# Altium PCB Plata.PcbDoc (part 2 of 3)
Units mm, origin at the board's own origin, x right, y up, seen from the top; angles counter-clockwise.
Board outline 225.2 x 126.25 mm, 5 copper layers (Top Layer, Mid-Layer 1, Mid-Layer 2, Mid-Layer 3, Bottom Layer); 204 components, 178 nets, 840 pads, 262 vias.
Unrouted connection lines stored in the file: 7.
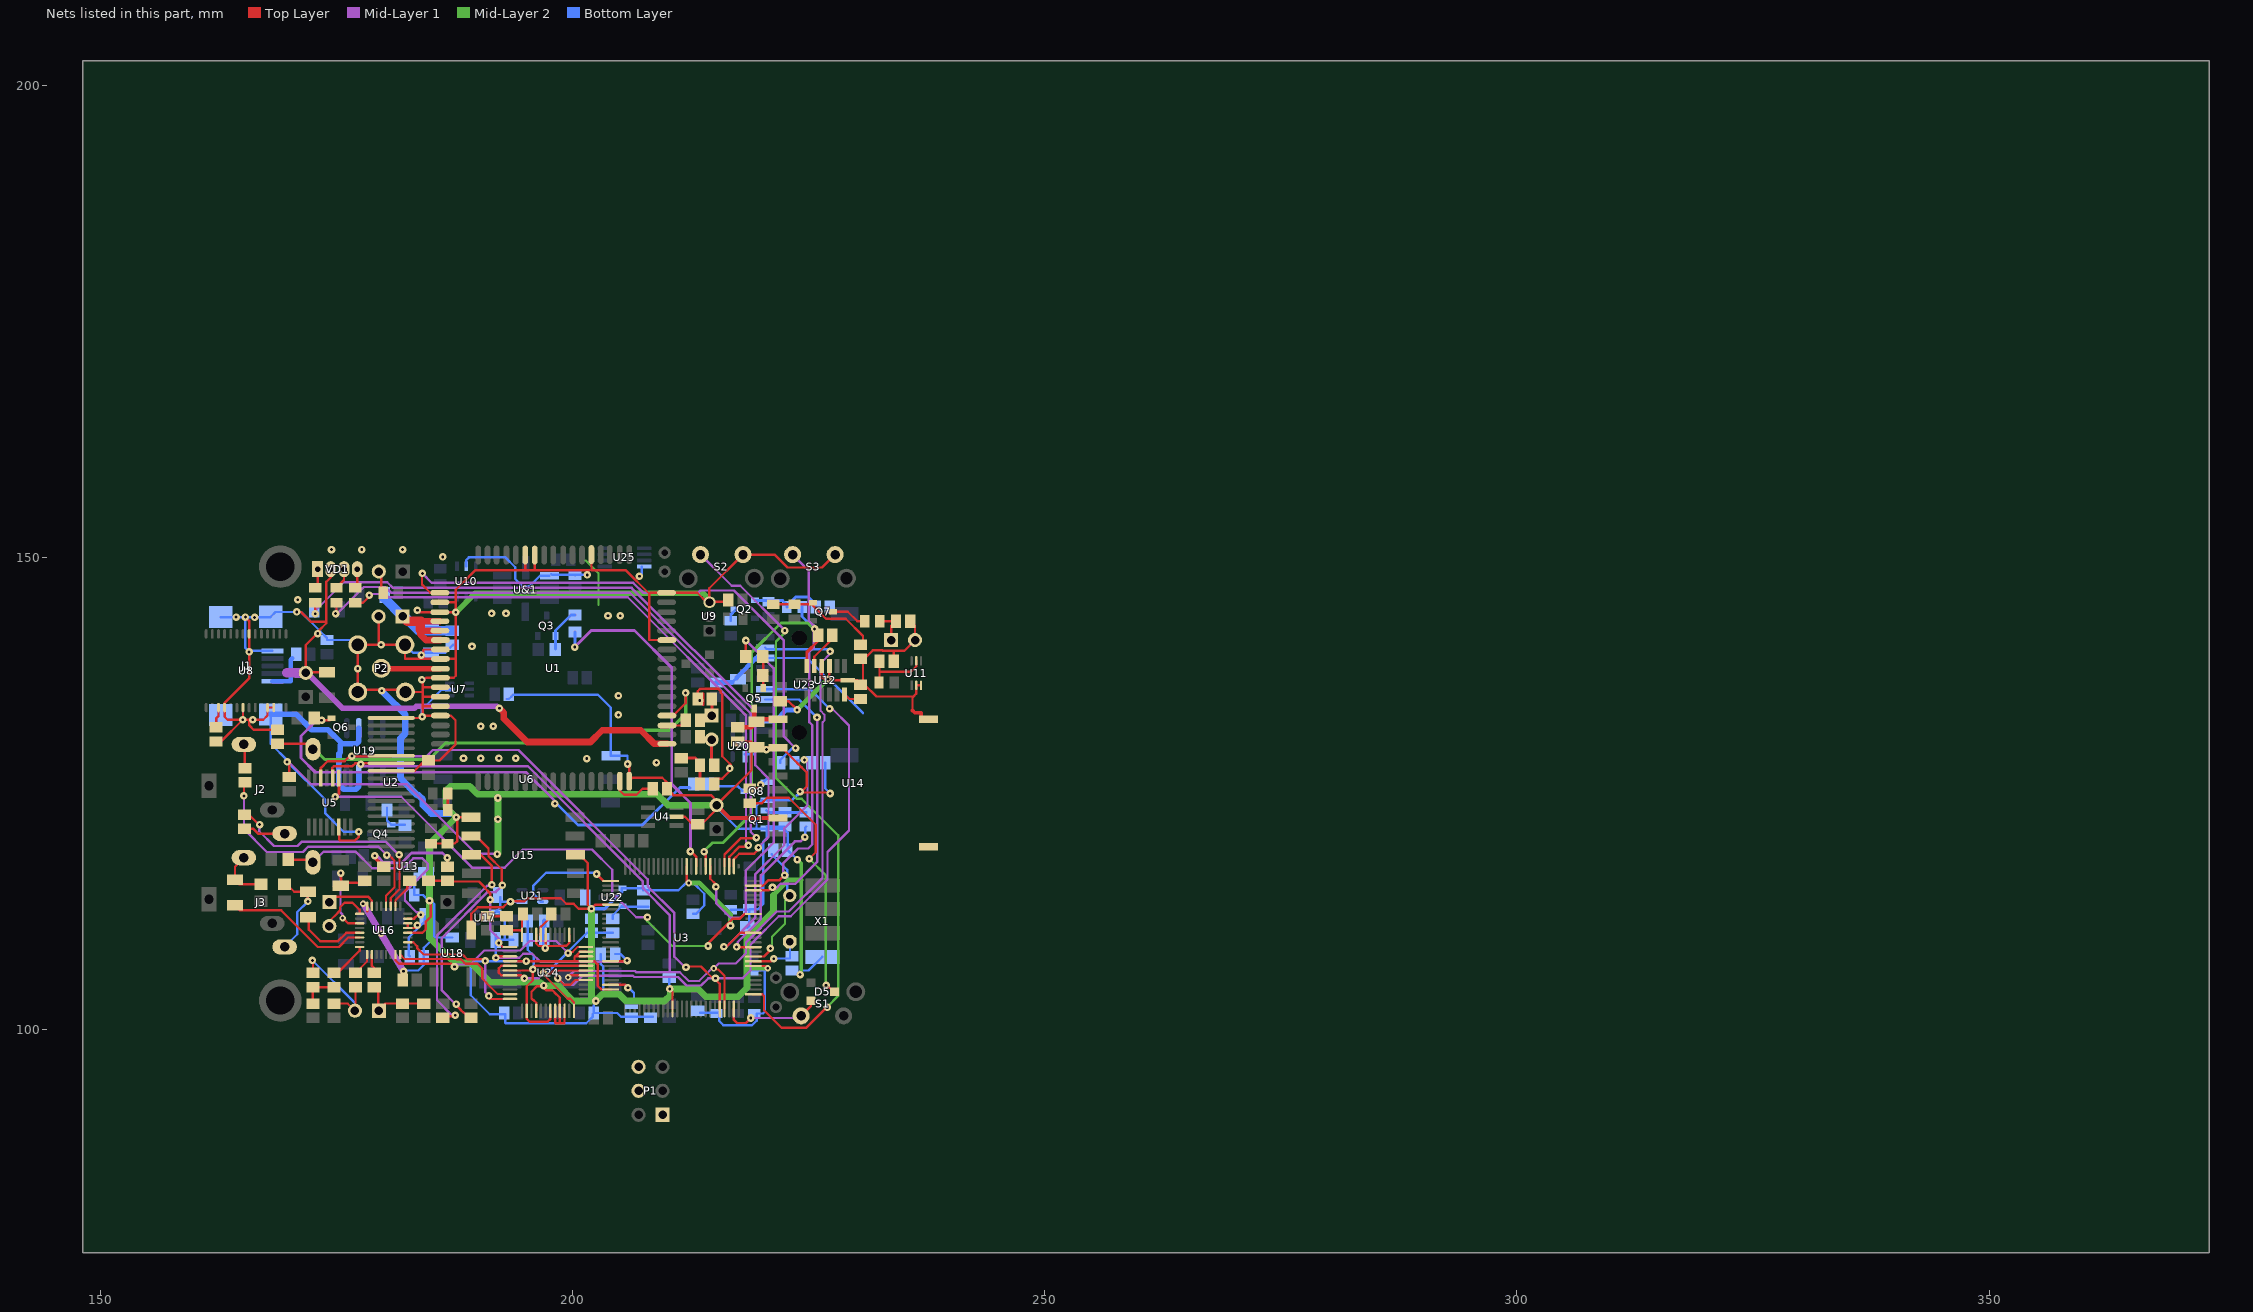
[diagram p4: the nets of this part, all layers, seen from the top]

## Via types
v1: diameter 0.8, hole 0.3, Top Layer to Bottom Layer, 158 vias
v2: diameter 0.8, hole 0.3, Top Layer to Mid-Layer 1, 69 vias
v3: diameter 0.8, hole 0.3, Mid-Layer 2 to Bottom Layer, 18 vias
v4: diameter 0.7, hole 0.3, Top Layer to Bottom Layer, 9 vias
v5: diameter 0.7, hole 0.3, Top Layer to Mid-Layer 1, 5 vias
v6: diameter 0.8, hole 0.3, Top Layer to Mid-Layer 1, tented top, 1 vias
v7: diameter 0.8, hole 0.3, Top Layer to Bottom Layer, tented top, 1 vias
v8: diameter 1, hole 0.5, Top Layer to Bottom Layer, 1 vias

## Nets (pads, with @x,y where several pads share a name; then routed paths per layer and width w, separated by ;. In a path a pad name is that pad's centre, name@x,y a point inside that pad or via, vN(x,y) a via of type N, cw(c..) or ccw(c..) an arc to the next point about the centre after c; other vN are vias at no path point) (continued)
GND: BT1.2 C1.1 C2.2 C3.2 C4.2 C5.2 C6.1 C7.1 C11.1 C12.2 C13.1 C14.2 C15.1 C16.2 C17.2 C18.1 C19.1 C20.2 C21.1 C22.1 C23.1 C24.1 C25.2 C26.1 C28.1 C31.2 C34.2 C38.2 C39.2 C43.1 C47.1 C48.2 C51.1 C55.1 C56.2 C57.2 C59.2 C60.1 C61.2 C62.2 C63.2 C64.2 C65.1 C66.1 C67.2 C68.1 C72.2 C73.2 D2.2 D4.1 J1.5 J1.MH1 J1.MH2 J1.MH3 J1.MH4 LS1.2 P1.6 P2.2 P2.3 P2.4 P2.5 Q1.2 Q8.2 R7.2 R8.2 R13.1 R14.1 R15.1 R16.1 R25.2 R49.1 R51.2 R56.1 S2.1 S3.1 U1.17 U1.29 U1.34 U1.39 U1.45 U1.46 U1.53 U1.54 U1.58 U1.59 U1.61 U1.62 U1.63 U1.64 U1.65 U2.1 U2.8 U3.11 U3.32 U3.62 U3.81 U3.99 U4.2 U5.6 U6.6 U7.2 U8.7 U8.18 U8.21 U8.25 U8.26 U9.3 U10.2 U11.2 U11.3 U12.7 U12.10 U12.11 U13.1 U14.3 U14.8 U14.11 U14.12 U15.3 U15.6 U16.12 U16.24 U17.1 U18.2 U19.3 U19.6 U20.1 U21.1 U22.1 U23.6 U23.9 U24.4 U24.16 U24.20 U24.21 U24.22 U24.33 U24.34 U24.35 U25.4 U&1.1 VD1.3 X1.8 | length 850.4
  Top Layer w0.25: C19.1@162.775,130.5 v1(165.075,132.8) ; U8.21@165.1,134.1 165.1,132.825 v1(165.075,132.8) ; v1(165.35,143.675) 165.75,143.275 U8.7@165.75,141.9 v1(165.75,140) 165.75,137.175 163.15,134.575 U8.18@163.15,134.1 163.15,133.125 163.475,132.8 v1(165.075,132.8) ; U8.26@168.35,134.1 U8.25@167.7,134.1 167.7,133.25 167.25,132.8 v1(166.125,132.8) v1@165.775,132.8 ; C43.1@168.75,131.75 166.225,131.75 165.775,132.2 v1@165.775,132.8 ; C14.2@170,126.75 v1@170,128.3 ; v1(170.8,144.225) 171.25,144.225 172.293,143.182 173.925,143.182 ; BT1.2@171.75,137.77 171.75,140.725 172.826,141.801 173.025,141.801 173.149,141.801 173.149,141.925 173.149,142.249 173.925,143.025 173.925,143.182 ; BT1.2@171.83,137.85 C62.2@174,137.85 ; VD1.3@174.4,148.75 174.4,147.88 173.925,147.405 173.925,143.182 ; U5.6@175.202,121.4 175.215,121.387 175.275,121.327 175.275,120.125 175.375,120.025 176.975,120.025 177.35,120.4 v1(177.35,120.95) ; v5@177.75,113.55 177.9,113.4 U16.24@178.25,113.05 178.25,112.532 ; v1@179.46,140.815 C2.2@179.46,143.75 ; U2.8@180.8,127.4 183.275,127.4 184.375,128.5 C5.2@184.75,128.5 185.905,128.5 187.6,130.195 187.6,132.75 187.1,133.25 U1.65@186,133.25 v1@184.17,133.25 ; U2.1@180.8,133 183.88,133 184.04,133.16 184.15,133.27 184.15,136.925 184.162,136.938 184.475,137.25 U1.61@186,137.25 187.4,137.25 187.625,137.475 v1(187.625,144.2) 187.625,146.575 189.675,148.625 201.55,148.625 201.8,148.625 ; C57.2@182,105.25 182,106.175 v1@182,106.25 ; U16.12@182.55,110.25 184.1,110.25 184.47,110.62 184.47,111.445 184.94,111.915 ; v1@183.688,144.287 183.775,144.2 U1.54@185.95,144.2 v1@187.575,144.2 ; 184.1,135.75 P2.3@182.3,135.75 182.05,136 179.8,136 177.25,136 v1(177.25,138.225) P2.5@177.25,140.75 v1(179.725,140.75) P2.4@182.25,140.75 182.25,139.25 184,139.25 184.2,139.25 ; 184.175,135.25 U1.63@186,135.25 ; 184.2,134.25 U1.64@186,134.25 ; 184.2,136.25 U1.62@186,136.25 ; 184.984,111.931 v1@184.984,113.291 ; R16.1@185,119.7 R15.1@186.75,119.7 187.525,119.7 187.8,119.975 v1@187.8,122.391 ; U1.53@185.95,145.25 187.55,145.25 ; U1.58@186,140.25 184.275,140.25 184.2,140.175 184.2,139.65 184.2,139.25 ; R14.1@186.8,123.25 R13.1@186.8,125 ; 187.625,139.25 U1.59@186,139.25 184.2,139.25 ; v1@187.909,122.5 U15.6@189.25,122.5 ; U18.2@189.282,110.54 189.282,112.257 189.975,112.95 192.65,112.95 v1@193.288,113.587 ; U24.4@193.375,107.25 v1(195.1,107.25) 200.2,107.25 ; v1@193.425,113.587 194.913,113.587 195.225,113.9 198.75,113.9 199.325,113.325 200.115,113.325 200.64,112.8 v1(202,112.8) ; 195,148.725 U1.46@195,150.25 ; 195.825,103.125 195.65,103.3 195.65,104.004 196.246,104.6 v1@196.775,104.6 ; 195.857,103.125 196.15,102.832 ; 196,148.725 U1.45@196,150.25 ; U24.16@196.15,101.975 196.15,102.8 ; v1@196.838,104.537 197.2,104.175 197.85,104.175 198.314,103.711 ; U24.20@198.15,101.975 198.15,100.75 198.25,100.65 199.125,100.65 199.15,100.675 U24.22@199.15,101.975 ; 198.325,103.711 198.65,103.386 U24.21@198.65,101.975 198.65,100.65 ; U15.3@200.3,118.5 200.725,118.5 201.6,117.625 201.6,113.2 v1(202,112.8) ; U24.34@201.425,107.75 200.3,107.75 ; U24.35@201.425,108.25 200.8,108.25 200.3,107.75 ; U1.39@202,150.3 202,148.625 205.65,148.625 208.125,146.15 ; U3.99@204.036,104.236 203.054,104.236 202.65,104.64 202.65,106.9 202.3,107.25 U24.33@201.425,107.25 200.2,107.25 ; U3.81@204.036,113.236 202.436,113.236 v1(202,112.8) ; v1(205.825,128.125) 206,127.95 U1.17@206,126.3 ; 206,127.4 U1.17@206,126.3 ; U1.29@210,141.25 208.125,141.25 208.125,146.15 ; U3.11@210.586,102.186 210.586,104.014 ; U4.2@211,122.55 211.875,122.55 212.675,121.75 C6.1@213.029,121.75 ; v4@212.086,115.525 U3.62@212.086,117.286 ; C6.1@213.25,121.75 213.675,121.75 215.25,123.325 LS1.2@215.25,123.77 ; U9.3@214.225,145.225 213.2,146.25 U1.34@209.95,146.25 208.225,146.25 208.125,146.15 ; U9.3@214.45,145.475 U9.3@214.475,145.475 ; C20.2@216.375,145.3 214.5,145.3 214.45,145.3 U9.3@214.475,145.475 ; C39.2@217.5,130.5 218.9,130.5 C38.2@219.5,129.9 219.55,129.85 220.525,129.85 U14.3@221.75,129.85 ; C38.2@218.95,129.6 218.95,127.47 LS1.2@215.25,123.77 ; U3.32@219.136,106.736 v4@220.675,106.736 ; U14.3@221.85,129.75 U14.3@221.75,129.85 ; C31.2@222,134.75 222.9,134.75 v1@223.7,133.95 ; U14.3@222.525,129.5 U14.3@222.525,129.505 ; U14.3@222.525,129.75 U14.3@222.525,129.505 ; U14.3@222.6,130.025 221.925,130.025 U14.3@221.75,129.85 ; v1@223.975,125.1 224.1,125.1 v1@224.15,125.1 ; v1@224.087,125.037 v1@224.15,125.1 ; U12.11@226.4,138.5 226.4,137.35 226.75,137 227.075,137 U12.7@229.15,137 230.175,137 230.588,136.587 230.675,136.5 230.95,136.5 232.175,135.275 236.1,135.275 ; v1@226.9,125.1 v1@224.15,125.1 ; v1@227.2,137.025 227.2,137.1 U12.10@227.2,138.5 ; S3.1@227.8,150.3 226.425,148.925 222.77,148.925 221.395,150.3 S2.1@218.05,150.3 214.475,146.725 U9.3@214.475,145.475 ; C28.1@231,136.5 230.75,136.75 230.75,139.25 230.875,139.25 231.78,140.155 232.795,140.155 232.825,140.125 235.145,140.125 D2.2@236.27,141.25 236.27,142.73 C55.1@235.75,143.25 ; C25.2@234,139 234,140.105 ; 236,133.775 236,135.175 236.1,135.275 ; U11.3@236.9,136.45 U11.2@236.4,136.45 236.4,135.575 236.1,135.275 ; U14.12@236.925,132.85 U14.12@237.7,132.85 ; v1(165.075,132.8) v1@165.775,132.8 ; 200.2,107.25 200.2,107.65 200.3,107.75 ; U1.17@206,126.3 206.375,126.675 209.5,126.675 210,126.175 C7.1@210,125.5 210.675,124.825 214.65,124.825 215.25,124.225 LS1.2@215.25,123.77 ; U14.3@221.75,129.85 222.18,129.85 U14.3@222.525,129.505 ; U14.3@222.525,129.505 223.775,128.255 223.775,128.229 224.229,127.775 224.255,127.775 224.8,127.23 224.8,125.75 224.175,125.125 v1@224.15,125.1
  Top Layer w0.4: LS1.2@215.25,123.77 216.62,122.4 219.836,122.4 ; 219.55,122.4 219.836,122.4 ; U14.8@221.75,122.4 219.836,122.4 ; 236,133.775 236.231,133.544 236.925,133.544 U14.12@236.925,132.85
  Mid-Layer 1 w0.25: v1@170,128.3 172.325,125.975 182.425,125.975 189.775,118.625 v1@191.7,118.625
  Mid-Layer 1 w0.6: BT1.2@171.557,138.093 171.815,137.835 171.9,137.75 174.282,135.368
  Mid-Layer 1 w0.7: v5(177.825,113.325) v4(179.719,110.157) 179.77,110.073 v1(182.1,106.175)
  Mid-Layer 1 w1: 169.75,137.77 BT1.2@171.75,137.77 ; 170.675,137.75 171.75,137.75 BT1.2@171.9,137.75
  Mid-Layer 2 w0.25: 201.4,149.675 202.75,148.325 202.75,146.2 202.75,145 ; v1@227.025,137.1 v1(227.075,137.1)
  Mid-Layer 2 w0.4: v1(223.8,118) 224.225,117.575 v1@224.225,105.95
  Mid-Layer 2 w0.5: v4(212.3,115.525) 213.425,115.525 216.725,112.225 v3(216.725,111) ; 218.525,106.5 v4(220.675,106.5) ; 221.275,114.225 222.9,115.85 224.225,115.85 ; v1(223.775,133.85) v1@227.025,137.1
  Mid-Layer 2 w0.6: v1@187.65,144.175 189.675,146.2 213.8,146.2 U9.3@214.5,145.5
  Mid-Layer 2 w0.7: v1@192.1,118.65 192.1,124.925 ; 196.461,105 191.3,105 189.25,107.05 187.525,107.05 184.85,109.725 v1(184.85,113.65) 184.85,119.65 v1(187.675,122.475) 186.6,123.55 186.6,125.3 187.05,125.75 189.125,125.75 189.95,124.925 192.1,124.925 ; 196.511,104.95 196.65,104.95 v1(196.95,104.65) 198.45,104.65 200.075,103.025 v3(202.475,103.025) 202,103.5 v1(202,112.8) ; v3@202.475,103.072 203.161,103.758 204.917,103.758 205.65,103.025 209.75,103.025 210.357,103.632 v1@210.357,103.943 ; v1(210.3,104.3) 213.311,104.3 214.136,103.475 217.519,103.475 218.475,104.431 218.475,109.725 221.275,112.525 221.275,114.225 ; LS1.2@215.25,123.77 210.109,123.77 208.954,124.925 192.1,124.925
  Bottom Layer w0.25: J1.MH3@162.737,143.675 v1(164.375,143.675) v1(165.35,143.675) ; J1.MH1@167.988,133.325 J1.MH1@168.038,133.375 168.038,130.262 v1@169.862,128.438 ; J1.5@168.213,140.1 165.75,140.1 165.65,140.1 165.35,140.4 v1(165.35,143.675) ; v1(169.775,128.35) 169.821,128.35 173.825,124.346 173.825,122.875 175.75,120.95 v1(177.35,120.95) ; P2.5@177.25,140.75 176.75,141.25 C18.1@174,141.25 174,141.475 173.287,142.188 171.25,144.225 v1(170.8,144.225) 168.538,144.225 J1.MH4@168.038,143.725 167.988,143.675 166.325,143.675 v1(165.35,143.675) ; v1@182,106.25 182.1,106.25 183.65,106.25 184.25,106.85 C34.2@184.25,107.75 184.25,108.65 185.35,109.75 ; P2.4@182.25,140.75 183.1,139.9 184,139.9 C4.2@185,139.9 186.5,139.9 187.3,140.7 C3.2@187.35,140.75 ; U13.1@183.45,116.2 183.25,116 C26.1@183.25,114.25 184.15,114.25 v1@184.65,113.75 ; v1@183.975,133.075 184.025,133.125 184.025,133.875 186.15,136 U7.2@186.98,136 ; v1@185,113.65 185.35,113.3 185.35,109.75 ; C48.2@187.25,109.75 185.35,109.75 ; 188.025,107.25 191.85,107.25 ; U10.2@188.75,149.05 188.75,149.725 189.025,150 192.888,150 193.925,148.963 193.925,147.725 194.7,146.95 195.45,146.95 196.55,148.05 U&1.1@197.55,148.05 ; 189.209,107.191 189.209,103.641 191.225,101.625 192.75,101.625 192.875,101.625 192.875,100.725 192.925,100.675 200.045,100.675 201.455,100.675 202.125,101.345 C72.2@202.125,101.625 ; C51.1@191.85,109.75 C51.1@191.85,109.5 ; C51.1@191.85,110.059 C51.1@191.85,109.5 ; C47.1@192.35,114 C47.1@192.35,113.55 ; 192.825,109.5 192.825,111.825 192.2,112.45 U17.1@191.85,112.45 192.35,112.95 C47.1@192.35,113.55 ; C13.1@193,135 193.25,135 193.5,135.25 193.725,135.475 202.675,135.475 204.05,134.1 U6.6@204.05,129 205.825,129 v1(205.825,128.125) ; C65.1@193.75,109.5 C51.1@191.85,109.5 ; U21.1@194.65,113.55 v1(193.425,113.55) C47.1@192.35,113.55 ; v1(195.1,107.25) 191.85,107.25 ; U&1.1@197.75,148.25 197.85,148.15 C21.1@200.25,148.15 ; C21.1@200.275,148.125 C21.1@200.25,148.15 ; v1(201.55,148.15) C21.1@200.25,148.15 ; C68.1@202,111.75 v1(202,112.8) ; R56.1@203,108 203,106.925 203.245,106.68 203.245,103.595 202.575,102.925 202.25,102.6 C72.2@202.25,101.75 204.725,101.75 205.125,101.35 206.25,101.35 208.25,101.35 R51.2@208.5,101.35 ; 205.2,114.6 205.2,114.95 U22.1@205.3,114.95 207.5,114.95 207.55,114.95 C63.2@207.625,114.875 ; v1(207.075,148) 207.325,148.25 U25.4@207.325,149.025 ; C63.2@207.5,114.75 211.225,114.75 212,115.525 v4(212.3,115.525) 212.8,115.525 213.95,114.375 213.95,113.142 213.058,112.25 C22.1@212.75,112.25 ; v1@210.25,104.35 C24.1@210.25,105.5 ; C11.1@213.525,101.775 215.25,101.775 215.475,101.775 215.525,101.725 215.525,101.7 215.525,100.9 215.975,100.45 219,100.45 219.5,100.95 219.5,101.7 220.168,101.7 220.35,101.882 220.35,106.15 ; LS1.2@215.25,123.77 215.25,123.55 217.525,121.275 219.475,121.275 ; v3(216.725,111) 216.725,112.675 R49.1@216.75,112.7 218.7,112.7 218.7,110.95 D4.1@218.5,110.75 ; C66.1@216.9,136.75 C66.1@217.375,137.225 ; U20.1@218.25,129.15 219.15,129.15 219.65,129.65 v1(220.525,129.65) ; C61.2@218.75,112.75 219.625,112.75 220.175,113.3 220.175,119.85 220.55,120.225 Q1.2@220.55,121.275 ; C23.1@219,106.25 v4@220.45,106.25 ; U23.6@219.443,139.35 U23.6@220.4,139.35 224.825,139.35 v1(227.075,137.1) ; Q8.2@220.075,124.3 219.475,123.7 219.475,121.275 ; Q1.2@220.55,121.3 Q1.2@220.55,121.275 ; Q1.2@220.55,121.5 R8.2@222.5,121.5 ; Q8.2@220.55,124.3 223.25,124.3 223.75,124.8 223.85,124.8 ; v1(223.8,118) 222.775,119.025 222.775,120.875 222.375,121.275 Q1.2@220.55,121.275 ; 224.1,106.25 225,106.25 X1.8@226.45,107.7 ; R7.2@226.75,128.25 226.75,125.525 v1(227.275,125) ; v1@227.3,136.975 230.763,133.513 ; 191.85,107.25 C51.1@191.85,109.5 ; 219.475,121.275 Q1.2@220.55,121.275
  Bottom Layer w0.4: v1(202,112.8) 203.4,112.8 205.2,114.6
  Bottom Layer w0.5: C67.2@215.25,136.75 C66.1@216.9,136.75 ; C66.1@217.375,137.225 217.375,137.282 U23.6@219.443,139.35 ; U23.9@220.4,132.75 221.55,132.75 222.65,133.85 v1(223.775,133.85)
  Bottom Layer w0.6: J1.MH1@168.038,133.375 170.75,133.375 172.375,131.75 174.108,131.75 175.577,130.28 ; 175.3,129.249 175.275,129.224 ; U19.3@177.365,127.1 177.365,125.74 177.075,125.45 175.743,125.45 175.245,125.948 175.245,128.252 175.275,128.282 175.275,129.224 ; U19.6@177.365,131.9 177.365,130.515 177.1,130.25 175.547,130.25 175.395,130.098 175.395,129.344 175.275,129.224
  Bottom Layer w0.7: v1@180.063,135.587 182.3,133.35 182.3,131.361 181.775,130.836 181.775,126.611 183.586,124.8 ; 183.706,124.8 184.15,124.356 184.15,123.751 185.026,122.875 187.275,122.875
  other v1: 224.1,105.825 192.025,118.575 192.1,122.275 192.1,124.525 224.1,125.2 201.5,128.7 188.45,128.725 190.275,128.725 192.2,128.725 193.975,128.725 190.275,132.125 191.6,132.125 184.075,133.125 204.85,133.325 204.85,135.35 179.8,135.875 184.05,137.05 184,139.65 189.35,140.575 173.025,141.925 166.325,143.65 203.75,143.825 205.05,143.825 191.425,144.075 192.95,144.075 183.575,144.4 170.9,145.525 186.25,150.05 174.475,150.825 177.675,150.825 182,150.825
GND1: C10.1 R23.1 U1.18 | length 58.6
  Top Layer w0.25: 213.825,134.375 213.825,134.85 213.825,135 213.825,135.575 213.288,135.037 R23.1@213.25,135 213.25,135.825 213.5,136.075 213.525,136.075 215.455,136.075 215.675,135.855 215.675,135.682 215.85,135.507 215.85,133.45 ; C10.1@215,126.5 215.075,126.575 215.85,126.575 216.65,127.375 v1(216.65,127.65) 216.65,128.15 ; 215.85,134.155 215.85,133.45 ; v1@216.775,128.025 216.65,128.15 ; 215.85,133.45 215.85,128.95 216.65,128.15
  Top Layer w0.7: v1(192.25,134.025) 192.712,133.563 192.712,132.938 195.2,130.45 201.9,130.45 203.15,131.7 207.225,131.7 208.675,130.25 U1.18@210,130.25
  Mid-Layer 1 w0.6: 172.9,136.75 175.625,134.025 183.25,134.025 183.45,134.225 191.975,134.225 v1@192.212,133.987
  other v1: 208.875,128.275 213.475,134.85
GPIO: J3.5 R40.2 U16.15 | length 25.5
  Top Layer w0.25: R40.2@169.9,118 172.2,118 J3.5@172.5,117.7 ; U16.15@182.55,111.75 183.225,111.75 183.632,112.157 183.918,112.157 183.921,112.154 183.925,112.15 v2(183.918,112.15)
  Mid-Layer 1 w0.25: J3.5@172.5,117.7 173.645,118.845 177.009,118.845 178.779,117.075 182.077,117.075 183.127,118.125 184.1,118.125 184.675,117.55 184.675,117 182.25,114.575 182.25,113.668 183.488,112.431 183.616,112.431 v2@183.896,112.15
GPS_ON: R35.2 U3.57 | length 41
  Top Layer w0.25: U3.57@214.586,117.286 214.586,115.964 215.175,115.375 v2(215.175,115.125) ; R35.2@218.35,139.5 v2(218.35,141.2)
  Mid-Layer 1 w0.25: v2@215.225,114.975 215.225,113.35 216.75,111.825 217.75,111.825 218.335,112.41 218.335,116.849 219.986,118.5 219.996,118.5 221.3,119.804 221.3,138.25 v2(218.35,141.2)
GSM_ON: R6.1 U3.36 | length 17.7
  Top Layer w0.25: v2(217.375,108.75) 217.389,108.736 U3.36@219.136,108.736
  Mid-Layer 1 w0.25: v2@217.5,108.95 217.5,109.267 219.945,111.712 219.945,116.328 223.542,119.925 224.15,119.925 v1(224.6,120.375)
  Bottom Layer w0.25: v1@224.65,120.375 224.65,121.4 R6.1@224.75,121.5
GSM_SPK1: C43.2 J2.5 U1.21 | length 51.5
  Top Layer w0.25: C43.2@168.75,130.25 171.95,130.25 J2.5@172.5,129.7 ; U1.21@210,133.25 210.1,133.35 210.775,133.35 211.975,134.55 v1@211.975,135.45
  Mid-Layer 2 w0.25: J2.5@172.5,129.7 J2.5@172.675,129.7
  Mid-Layer 2 w0.35: J2.5@172.675,129.7 173.775,128.6 184.825,128.6 186.575,130.35 201.8,130.35 203.15,131.7 210.225,131.7 211.975,133.45 v1(211.975,135.65)
HP_OUT_L: C49.1 U16.30 | length 15.4
  Top Layer w0.25: C49.1@164.25,113.15 164.775,112.625 169.15,112.625 173.025,108.75 175.254,108.75 176.254,109.75 U16.30@177.45,109.75
HP_OUT_R: C50.1 U16.29 | length 7.6
  Top Layer w0.25: C50.1@172.075,111.975 172.075,111.9 172.075,110.575 173.285,109.365 175.162,109.365 176.047,110.25 U16.29@177.45,110.25
I2C_AUDIO_CLK: U16.8 U24.11 | length 14
  Top Layer w0.22: U16.8@181.75,107.95 182.24,107.46 187.7,107.46 ; 190.92,104.905 192.075,103.75 U24.11@193.375,103.75
  Top Layer w0.24: 187.7,107.46 188.154,107.46 188.657,106.957 189.935,106.957 190.425,106.467 190.425,105.4 190.92,104.905
I2C_AUDIO_DAC: U16.10 U24.12 | length 15.2
  Top Layer w0.22: v2@191.2,103.25 U24.12@193.375,103.25
  Top Layer w0.24: U16.10@182.55,109.25 182.555,109.245 183.13,109.245 183.539,108.836 183.539,108.636 184.235,107.94 187.487,107.94 187.497,107.95 188.357,107.95 188.86,107.447 190.578,107.447 v2(190.75,107.275)
  Mid-Layer 1 w0.22: v2(190.75,107.275) 190.75,103.95 v2(191.129,103.571)
I2C_AUDIO_LR: U16.7 U24.36 | length 23.2
  Top Layer w0.22: U16.7@181.25,107.95 181.25,107.35 181.62,106.98 ; v2@199.525,108.225 200.025,108.225 200.55,108.75 U24.36@201.425,108.75
  Top Layer w0.24: 181.62,106.98 187.17,106.98 v2(187.5,106.65)
  Mid-Layer 1 w0.22: v2@187.638,106.83 187.723,106.915 187.765,106.915 187.75,106.9 189.175,106.9 190.65,108.375 194.443,108.375 195.453,109.385 198.265,109.385 199.245,108.405 v2@199.245,108.1 ; v2@199.338,107.988 199.338,108.1 199.338,108.287 199.4,108.35 v2@199.525,108.225
  other v2: 199.525,108.1
I2C_MODULE_POWER: R30.2 U3.60 | length 36.2
  Top Layer w0.25: v2@212.638,118.775 213.086,118.327 U3.60@213.086,117.286
  Mid-Layer 1 w0.3: v1(200.225,140.5) 201.975,142.25 206.566,142.25 210.5,138.316 210.5,125.975 212.485,123.99 v2(212.485,118.856)
  Bottom Layer w0.3: v1@200.25,140.5 R30.2@200.25,142.1
INT_TC: U3.43 U5.11 | length 57.7
  Top Layer w0.25: v1@214.25,108.775 214.25,108.85 214.25,109.025 216.95,111.725 217.685,111.725 218.196,112.236 U3.43@219.136,112.236
  Top Layer w0.3: v2@175.05,124.775 175.252,124.977 U5.11@175.252,126.6
  Mid-Layer 1 w0.25: v2(174.875,124.65) 181.85,124.65 189.345,117.155 192.815,117.155 194.724,119.064 202.057,119.064 204.2,116.921 204.2,114.45 206.75,111.9 v1(207.925,111.9)
  Mid-Layer 2 w0.25: v1(207.925,111.9) 207.925,111.475 210.55,108.85 v1(214.35,108.85)
KEY_1: D5.2 S1.1 U3.24 | length 10.8
  Top Layer w0.25: U3.24@217.086,102.186 217.086,101.014 217.4,100.7 218.35,100.7 v2(218.875,101.225) ; S1.1@224.2,101.45 225.25,102.5 D5.2@225.25,103.05
  Mid-Layer 1 w0.25: v2@218.825,101.275 v2(218.875,101.225) 223.35,101.225 223.517,101.392 224.142,101.392 S1.1@224.2,101.45
KEY_2: S2.2 U3.26 | length 67.4
  Top Layer w0.25: U3.26@219.136,103.736 220.089,103.736 220.275,103.55 220.275,102.05 222.15,100.175 224.728,100.175 226.903,102.35 v1(226.975,102.35)
  Mid-Layer 1 w0.25: S2.2@213.55,150.3 216.855,146.995 217.755,146.995 222.234,142.516 222.434,142.516 222.434,142.25 v1@222.434,142.232
  Mid-Layer 2 w0.25: v1@222.661,142.232 222.661,142.211 222.587,142.138 221.55,141.1 221.55,126.654 223.779,124.425 224.275,124.425 228.125,120.575 228.125,103.55 227,102.425 226.975,102.425 v1@226.85,102.425
  other v1: 222.475,142.25
KEY_3: S3.2 U3.49 | length 40.9
  Top Layer w0.25: U3.49@219.136,115.236 220.161,115.236 220.75,115.825 221.496,115.825 221.925,115.825 v2(222.45,116.35)
  Mid-Layer 1 w0.25: v2@222.3,116.325 222.3,116.35 222.3,117.596 223.884,119.18 224.959,119.18 225.375,119.596 225.375,132.25 225.075,132.55 225.075,140 225.525,140.45 225.525,142.8 225.025,143.3 225.025,148.575 S3.2@223.3,150.3
LCD_LIGHT_1: R20.1 U3.58 | length 36.5
  Top Layer w0.25: v1(213.925,118.825) 214.086,118.664 U3.58@214.086,117.286
  Mid-Layer 2 w0.3: v1@213.925,118.9 214.8,119.775 215.9,119.775 218.975,122.85 218.975,139.95 222.075,143.05 224.9,143.05 v3@225.475,142.475
  Bottom Layer w0.3: R20.1@224.3,145 R20.1@224.3,144.75 224.3,143.75 v3(225.625,142.425)
LED_B: R2.1 U3.54 | length 70.8
  Top Layer w0.25: v2@175,143.975 175,144.05 R2.1@175,145.2 ; U3.54@216.086,117.286 216.086,118.536 217.825,120.275 219.317,120.275 219.371,120.221 v1@219.511,120.081
  Mid-Layer 1 w0.25: v2@175,143.975 177.895,146.87 180.173,146.87 180.768,146.275 206.05,146.275 218.865,133.46 218.865,120.935 v1(219.475,120.325) ; v1@219.3,120.15 v1@219.4,120.05
  other v2: 174.9,144.05
LED_G: R1.1 U3.53 | length 64.5
  Top Layer w0.25: R1.1@177,145.2 177.8,145.2 178.475,145.875 v2(178.475,146) ; U3.53@216.586,117.286 216.586,118.286 217.675,119.375 v1@218.625,119.375
  Mid-Layer 1 w0.25: v2@178.475,146.125 179.82,146.125 180.17,145.775 205.843,145.775 218.365,133.253 218.365,119.76 v1(218.625,119.5)
LED_R: R4.1 U3.52 | length 74.1
  Top Layer w0.25: v2(172.75,144.025) R4.1@172.75,145.2 ; U3.52@217.086,117.286 217.086,118.061 217.65,118.625 219.225,118.625 v2@219.65,119.05
  Mid-Layer 1 w0.25: v2(172.75,144.025) 172.75,144.35 175.77,147.37 180.38,147.37 180.975,146.775 206.258,146.775 219.365,133.668 219.365,127.985 220.75,126.6 220.75,120.4 219.925,119.575 v2@219.925,119.275
  other v2: 219.675,119.275
LINE_IN1: C74.1 R59.2 U24.1 | length 14.3
  Top Layer w0.25: C74.1@184.75,115.75 R59.2@186.75,115.75 186.795,115.705 R59.2@187.125,115.705 ; R59.2@187.125,115.85 187.125,115.75 R59.2@187.125,115.705 ; v2(191.275,113.75) 191.275,114.463 191.182,114.556 191.138,114.556 190.684,115.01 190.684,115.096 190.105,115.675 187.155,115.675 R59.2@187.125,115.705 ; v2(192.175,109.175) 192.6,108.75 U24.1@193.375,108.75
  Mid-Layer 1 w0.25: v2(191.275,113.75) 191.275,110.55 192.175,109.65 v2(192.175,109.175)
LINE_IN2: C75.2 R60.2 U24.48 | length 4
  Top Layer w0.25: R60.2@193,110.5 194.525,110.5 U24.48@194.65,110.375 ; U24.48@194.65,110.025 U24.48@194.65,110.375 ; C75.2@194.75,112.25 194.65,112.15 U24.48@194.65,110.375
LINE_IN_L: C40.1 U16.20 | length 27.8
  Top Layer w0.25: v2(165.2,124.75) 165.2,126.088 C40.1@165.299,126.187 ; U16.20@180.25,113.05 180.25,114.175 181.15,115.075 181.15,117.88 180.855,118.175 180.854,118.175 180.85,118.179 180.85,118.2 180.65,118.4 v2@180.5,118.4
  Mid-Layer 1 w0.25: v2(165.2,124.75) 165.2,121.225 167.625,118.8 171.438,118.8 172.013,119.375 179.425,119.375 v2(180.325,118.475)
LINE_IN_R: C41.1 U16.19 | length 24.8
  Top Layer w0.25: C41.1@165.25,122.75 165.75,122.75 166.825,121.675 166.856,121.706 v2(166.858,121.706) ; U16.19@180.75,113.05 180.75,113.925 181.675,114.85 181.675,118.175 181.489,118.361 v2@181.475,118.375
  Mid-Layer 1 w0.25: v2(166.858,121.706) 166.856,121.706 166.825,121.675 166.825,121 168.393,119.432 170.862,119.432 171.305,119.875 180.25,119.875 181.625,118.5 181.631,118.506 v2(181.634,118.506)
MICBIAS: R37.1 U16.32 | length 4.1
  Top Layer w0.25: R37.1@174.75,106 175.1,106 177.45,108.35 U16.32@177.45,108.75
MISO: P1.1 U2.7 U3.22 U5.12 U23.7 U24.30 | length 124
  Top Layer w0.22: v5@199.675,105.75 U24.30@201.425,105.75 ; v4@215.2,106.375 215.4,106.375 216.086,105.689 U3.22@216.086,102.186
  Top Layer w0.25: U5.12@174.567,126.6 174.567,126.625 174.567,127.717 174.75,127.9 176.699,127.9 176.999,128.2 177.575,128.2 U2.7@180.8,128.2
  Mid-Layer 1 w0.22: 211.352,106.08 212.282,105.15 213.414,105.15 v4@214.764,106.5 ; 226.465,132.515 226.66,132.71 226.66,133.357 226.275,133.742 226.275,138.8 v1@227.4,139.925
  Mid-Layer 1 w0.24: v5@199.525,105.575 200.152,106.202 206.6,106.202 206.722,106.08 211.352,106.08 211.366,106.08 211.423,106.023 ; v4(214.95,106.475) 215.48,107.005 217.269,107.005 218.355,108.091 218.355,109.215 221.635,112.495 222.906,112.495 226.465,116.054 226.465,132.515
  Mid-Layer 1 w0.25: v2@177.775,127.9 195.246,127.9 207.45,115.696 207.45,114.965 210.28,112.135 210.28,106.15
  Bottom Layer w0.24: U23.7@220.4,140.45 220.57,140.28 227.045,140.28 v1(227.275,140.05) v1@227.275,140.15
  Bottom Layer w0.25: v1@227.4,139.925 v1@227.525,140.05
  other v2: 177.575,128.1
  other v5: 199.525,105.525
MMC_CS: U3.48 U23.2 | length 29.7
  Top Layer w0.25: U3.48@219.136,114.736 220.761,114.736 v2@220.975,114.95
  Mid-Layer 1 w0.25: v2@220.975,114.95 221.175,114.95 221.532,114.95 222.032,115.45 223.6,115.45 225.9,117.75 v1@225.9,133.025 ; v1(225.886,133.056) 225.886,133.039 v1@225.9,133.025 ; v1@225.9,133.15 225.9,133.056 v1@225.9,133.025
  Bottom Layer w0.25: U23.2@220.4,134.95 223.993,134.95 v1(225.886,133.056) ; v1@225.886,133 v1@225.9,133
  other v2: 221.175,115.05
MOSI: P1.5 U2.6 U3.21 U5.14 U23.3 U24.29 | length 131.5
  Top Layer w0.25: U5.14@173.347,126.625 173.347,127.712 174.05,128.415 175.86,128.415 176.375,128.93 176.634,128.93 v2@176.675,128.93 ; v2(176.634,128.956) 176.649,128.956 v2@176.675,128.93 ; U2.6@180.8,129 180.73,128.93 v2@176.675,128.93 ; v2(198.425,105.45) 199.12,104.755 199.78,104.755 200.275,105.25 U24.29@201.425,105.25 ; v2@211.995,106.595 212.008,106.608 212.085,106.685 213.59,106.685 214.845,105.43 v1(215.135,105.43) ; v1@215.065,105.36 215.586,104.839 U3.21@215.586,102.186
  Mid-Layer 1 w0.25: v2(176.634,128.956) 176.66,128.93 184.531,128.93 185.201,129.6 194.261,129.6 207.95,115.911 207.95,115.172 210.78,112.342 210.78,107.72 v2@211.737,106.763 ; v2(198.425,105.45) 199.13,104.745 200.084,104.745 201.046,105.707 206.395,105.707 206.532,105.57 209.767,105.57 209.772,105.575 210.828,105.575 210.833,105.57 211.176,105.57 212.081,104.665 213.615,104.665 214.38,105.43 v1(215.135,105.43) 217.191,105.43 217.809,105.43 218.005,105.43 218.85,106.275 218.85,108.979 219.175,109.304 219.175,109.335 221.84,112 223.111,112 227,115.889 227,118.789 229.275,121.064 229.275,132.204 227.504,133.975 v1(227.225,133.975) v1@227.366,133.975
  Bottom Layer w0.25: U23.3@220.4,136.05 225.15,136.05 v1(227.225,133.975)
  other v2: 212.01,106.605
MP3_POW: U3.76 U21.4 | length 11.1
  Top Layer w0.25: v1(202.55,116.475) 203.289,115.736 U3.76@204.036,115.736
  Bottom Layer w0.25: U21.4@196.85,113.55 196.65,113.55 195.852,114.348 195.852,115.252 197.2,116.6 v1@202.375,116.6
MP3_RESET: R56.2 U3.93 U24.3 | length 19.4
  Top Layer w0.25: v2@191.975,107.75 U24.3@193.375,107.75 ; U3.93@204.036,107.236 205.711,107.236 v1(205.775,107.3)
  Mid-Layer 1 w0.25: v2@191.875,107.396 v2(191.875,107.6) 194.354,107.6 194.779,108.025 195.732,108.025 196.557,107.2 v1@205.775,107.2
  Bottom Layer w0.25: R56.2@204.5,108 205.075,108 v1(205.775,107.3)
NetC2_1: C2.1 C3.1 C4.1 L1.2 U1.55 U1.56 U1.57 | length 18.1
  Top Layer w0.25: 183.875,142.35 183.975,142.25
  Top Layer w0.55: 183.875,143.2 183.925,143.25
  Top Layer w0.7: 183.875,142.35 183.875,141.85 184.475,141.25 U1.57@186,141.25 ; 183.925,143.25 U1.55@185.95,143.25 ; 183.975,142.25 U1.56@185.95,142.25
  Top Layer w1: C2.1@182.5,143.25 183.925,143.25 183.95,143.25 ; 183.875,142.35 183.875,143.2
  Bottom Layer w1: L1.2@180,145.75 C2.1@182,143.75 182.2,143.75 183.7,142.25 185,142.25 C3.1@187.25,142.25
NetC7_2: C7.2 U1.16 | length 4.9
  Top Layer w0.25: U1.16@205,126.3 205,125.325 205.45,124.875 206.775,124.875 207.4,125.5 C7.2@208.5,125.5
NetC8_1: C8.1 MK1.2 R19.1 | length 2.6
  Top Layer w0.3: MK1.2@214.725,130.71 214.725,128.525 R19.1@215,128.25
NetC9_1: C9.1 MK1.1 R23.2 | length 1.8
  Top Layer w0.3: MK1.1@214.725,133.25 214.75,133.275 R23.2@214.75,135
NetC9_2: C9.2 U1.20 | length 2.2
  Top Layer w0.25: U1.20@210,132.2 211.45,132.2 C9.2@212,132.75
NetC10_2: C10.2 R18.1 R19.2 | length 4
  Top Layer w0.3: R18.1@211.5,128.75 213,128.75 213.5,128.25 R19.2@213.5,128 C10.2@213.5,126.5
NetC12_1: C12.1 Q2.1 R20.2 R22.1 | length 7.7
  Bottom Layer w0.3: Q2.1@219.3,145.45 220.75,145.45 222.25,145.45 R20.2@222.7,145 ; R20.2@222.7,144.75 222.7,144.866 223.634,145.8 224.966,145.8 225.75,145.016 C12.1@225.75,144.75
NetC15_2: C15.2 U3.98 | length 3.9
  Top Layer w0.25: U3.98@204.036,104.736 U3.98@204.775,104.736 ; 204.976,104.736 U3.98@204.775,104.736 ; v1@205.961,104.289 205.85,104.4 v1(205.867,104.432) 205.575,104.724 205.575,104.736 U3.98@204.775,104.736
  Bottom Layer w0.25: v1@206.025,104.35 206.5,103.875 C15.2@206.5,103
NetC16_1: C16.1 U3.34 Y2.2 | length 13.6
  Top Layer w0.25: U3.34@219.136,107.736 220.286,107.736 v1@221.025,108.475
  Mid-Layer 2 w0.25: v1@221.125,108.55 221.125,108.6 221.125,109.825 222.5,111.2 222.5,114.19 Y2.2@222.5,114.44
  Bottom Layer w0.25: C16.1@221.075,118.575 222.72,116.93 222.72,114.66 222.625,114.565 Y2.2@222.5,114.44
  other v1: 220.95,108.6
NetC17_1: C17.1 U3.33 Y2.1 | length 6.3
  Top Layer w0.25: U3.33@219.136,107.236 221.036,107.236 v1(221.3,107.5)
  Bottom Layer w0.25: v1@221.3,107.525 223.025,107.525 223.025,107.75 223.025,109.035 222.875,109.185 Y2.1@222.5,109.56
NetC19_2: C19.2 U8.17 | length 2.2
  Top Layer w0.25: C19.2@162.25,132 162.25,132.95 162.5,133.2 U8.17@162.5,134.1
NetC25_1: C25.1 R32.1 U11.5 | length 6.9
  Top Layer w0.25: R32.1@232.5,136.8 232.5,137.875 ; C25.1@232.5,139 232.5,137.875 ; U11.5@236.4,139.05 236.4,138.51 236.4,138.468 235.807,137.875 232.5,137.875
NetC27_1: C27.1 U12.13 | length 3.7
  Top Layer w0.3: U12.13@224.8,138.5 224.8,139.95 226,141.15 C27.1@226,141.75
NetC27_2: C27.2 U12.12 | length 4
  Top Layer w0.25: U12.12@225.6,138.5 225.6,139.471 227.5,141.371 C27.2@227.5,141.75
NetC28_2: C28.2 U12.6 | length 2.4
  Top Layer w0.25: U12.6@228.8,135.5 229.3,135 C28.2@230.5,135 C28.2@231,135
NetC29_1: C29.1 U15.8 | length 23.1
  Top Layer w0.25: C29.1@186.225,101.4 186.25,101.4 v2@187.475,101.4 ; U15.8@189.3,118.5 189.325,118.475 190.3,118.475 191.459,117.316 v2(191.459,115.331) ; v2@191.377,115.248 v2@191.389,115.236
  Mid-Layer 1 w0.25: v2@187.35,101.4 185.645,103.105 185.645,109.945 190.936,115.236 v2@191.389,115.236
  other v2: 187.575,101.525
NetC30_1: C30.1 U15.7 | length 25.1
  Top Layer w0.25: v2@187.7,102.6 187.7,102.562 188.175,102.087 188.175,102.045 188.395,101.825 188.437,101.825 189.012,101.25 C30.1@189.25,101.25 ; U15.7@189.25,120.5 189.775,120.5 191.1,119.175 191.1,118.382 192.5,116.982 v2@192.5,115.5
  Mid-Layer 1 w0.25: v2@187.7,102.6 187.637,102.663 186.16,104.14 186.16,109.731 190.985,114.556 191.856,114.556 192.4,115.1 v2@192.4,115.125
  other v2: 187.675,102.7 192.575,115.275
NetC34_1: C34.1 L3.2 U16.13 U16.14 | length 6.8
  Top Layer w0.25: U16.14@182.55,111.25 U16.13@182.55,110.75 183.575,110.75 v1@183.6,110.75
  Bottom Layer w0.25: C34.1@182.75,107.75 182.65,107.85 182.65,109.75 183.075,110.175 ; 183.25,110.35 183.075,110.175 ; L3.2@184.35,112 184.35,111.45 183.762,110.863 183.075,110.175
  other v1: 183.575,111.05
NetC37_1: C37.1 R36.2 R37.2 | length 4
  Top Layer w0.25: C37.1@172.5,102.75 R36.2@172.5,104.5 R37.2@174.75,104.5
NetC38_1: C38.1 C39.1 Q5.3 U14.1 | length 6
  Top Layer w0.5: C39.1@217.5,132 218.9,132 C38.1@219.5,132.6 ; Q5.3@219.25,133.9 219.25,132.85 C38.1@219.5,132.6 ; U14.1@221.75,132.85 219.75,132.85 C38.1@219.5,132.6
NetC40_2: C40.2 J2.2 | length 2.6
  Top Layer w0.25: J2.2@165.2,130.2 165.299,130.101 C40.2@165.299,127.687
NetC41_2: C41.2 J2.4 | length 4.5
  Top Layer w0.25: C41.2@165.25,121.25 166.196,121.25 166.696,120.75 J2.4@169.5,120.75
NetC42_2: C42.2 C44.1 MK2.2 R36.1 | length 13.5
  Top Layer w0.22: v1@172.45,107.2 172.5,107.15 R36.1@172.5,106 ; C42.2@174.75,102.75 176.21,102.75 MK2.2@176.96,102 177,102.04 C44.1@177,104.5
  Bottom Layer w0.22: v1(172.45,107.325) 176.96,102.815 MK2.2@176.96,102
NetC44_2: C44.2 U16.1 | length 2.5
  Top Layer w0.22: C44.2@177,106 177.025,106 178.25,107.225 U16.1@178.25,107.95
NetC45_1: C45.1 C46.2 MK2.1 R39.2 | length 7.5
  Top Layer w0.22: MK2.1@179.425,102.125 C45.1@179.425,104.5 ; MK2.1@179.5,102 179.5,102.125 180.125,102.75 C46.2@182,102.75 R39.2@184.25,102.75
NetC45_2: C45.2 U16.2 | length 2.3
  Top Layer w0.25: U16.2@178.75,107.95 178.75,106.75 179.25,106.25 C45.2@179.5,106
NetC49_2: C49.2 J3.2 R41.1 | length 5.7
  Top Layer w0.25: J3.2@165.2,118.2 164.25,117.25 C49.2@164.25,115.85 164.7,115.4 R41.1@167,115.4
NetC50_2: C50.2 J3.4 R42.1 | length 9.7
  Top Layer w0.25: R42.1@169.5,115.4 169.725,115.4 170.525,114.6 C50.2@172,114.6 171.975,114.575 v1(171.975,113.575)
  Bottom Layer w0.25: J3.4@169.5,108.75 170.85,110.1 170.85,112.45 v1(171.975,113.575)
NetC52_1: C52.1 C53.1 U16.27 | length 10
  Top Layer w0.25: 175.4,116.15 175.5,116.05 C52.1@175.5,115.55 ; C52.1@175.5,115.4 C52.1@175.5,115.55 ; v5(175.65,111.8) 175.675,111.8 176.225,111.25 U16.27@177.45,111.25 ; C53.1@177.75,115.5 177.7,115.55 C52.1@175.5,115.55
  Mid-Layer 1 w0.25: v2@175.425,116.575 175.425,112.4 175.625,112.2 175.625,111.95 175.562,111.888 v5@175.475,111.8
  other v2: 175.45,116.575
NetC54_1: C54.1 U16.18 | length 3.2
  Top Layer w0.25: U16.18@181.25,113.05 181.25,113.7 182.5,114.95 C54.1@182.5,115.75
NetC55_2: C55.2 D2.1 R45.2 | length 3.9
  Top Layer w0.25: R45.2@232.55,143.25 C55.2@234.25,143.25 233.73,142.73 D2.1@233.73,141.25
NetC60_2: C60.2 Q7.1 R48.2 R50.2 | length 11.8
  Top Layer w0.25: R48.2@221.25,145.05 R50.2@223.5,145.05 225.3,145.05 226.85,143.5 228.925,143.5 230.75,141.675 C60.2@230.75,140.75
NetC63_1: C63.1 L8.2 U22.2 | length 4.5
  Bottom Layer w0.25: L8.2@204.25,111.75 204.25,112.1 205.2,113.05 205.25,113 205.3,113 207.5,113 C63.1@208,113
NetC65_2: C65.2 L7.1 U24.6 U24.14 U24.19 U24.32 | length 23
  Top Layer w0.25: U24.6@193.375,106.25 v1@195.8,106.25 ; 197.65,101.095 197.65,101.118 ; U24.19@197.65,101.225 197.65,101.118 ; U24.19@197.65,101.975 197.65,101.118 ; U24.32@201.425,106.75 196,106.75 195.8,106.55 v1(195.8,106.375) v1@195.8,106.25 ; v1@195.8,106.25 195.8,105.229 195.15,104.579 U24.14@195.15,101.975 195.15,101.118 195.443,100.825 197.357,100.825 197.65,101.118
  Bottom Layer w0.25: L7.1@195.25,111.5 C65.2@195.25,109.5 195.25,108.45 195.875,107.825 195.875,106.6 195.845,106.57 195.845,106.42 v1(195.8,106.375)
NetC68_2: C68.2 L8.1 U24.5 U24.7 U24.24 U24.31 | length 26.9
  Top Layer w0.25: 192.525,106.75 U24.5@193.375,106.75 192.45,106.75 192.2,106.5 192.2,105.99 192.44,105.75 U24.7@193.375,105.75 194.55,105.75 v2@194.825,105.475 ; U24.24@200.15,101.975 200.15,102.875 199.77,103.255 199.488,103.255 196.947,105.796 196.925,105.796 v1(196.925,105.95) 197.7,105.95 197.95,106.2 198,106.25 U24.31@201.425,106.25
  Mid-Layer 1 w0.25: v2(194.9,105.425) 195.475,105.45 196.425,105.45 v1(196.925,105.95)
  Bottom Layer w0.25: v1(196.925,105.95) 197.225,105.95 201.525,110.25 C68.2@202,110.25 L8.1@204.25,110.25
NetC69_2: C69.2 L9.1 U24.38 U24.43 U24.45 | length 9.2
  Top Layer w0.24: 199,108.85 199.02,108.87 199.345,108.87 199.65,109.175 U24.38@199.65,110.025
  Top Layer w0.25: U24.45@196.15,110.025 196.15,109.125 196.425,108.85 v1@196.95,108.85 ; v1@197.1,108.85 199,108.85 ; 197.15,109.05 U24.43@197.15,110.025
  Bottom Layer w0.5: L9.1@197,111.5 C69.2@197,109.5 197,108.725 v1(197.1,108.625)
NetC70_1: C70.1 U24.44 | length 2.7
  Top Layer w0.25: U24.44@196.65,110.025 196.65,110.875 196.65,110.882 196.943,111.175 196.955,111.175 197.75,111.97 C70.1@197.75,112.25
NetC71_1: C71.1 R59.1 | length 11.2
  Top Layer w0.3: v2@178.95,118.3 C71.1@180,117.25 ; R59.1@186.725,117.1 186.725,117.25 v2(186.725,118.2)
  Mid-Layer 1 w0.3: v2(179.05,118.4) 179.311,118.4 179.311,118.358 179.994,117.675 181.934,117.675 182.959,118.7 186.225,118.7 v2(186.725,118.2)
NetC76_1: C76.1 R60.1 | length 2
  Top Layer w0.25: C76.1@191,112 R60.1@193,112
NetD3_2: D3.2 R44.1 | length 2.3
  Top Layer w0.25: D3.2@179.73,148.5 179.73,146.47 R44.1@179.95,146.25
NetD5_3: D5.3 R52.2 | length 27.5
  Top Layer w0.25: R52.2@218.75,123.95 220.012,123.95 220.607,124.545 222.885,124.545 225.75,121.68 225.75,118.775 v1(225.057,118.082) v1@224.9,117.925 ; v1(226.85,104.7) 226.95,104.7 227.65,104 D5.3@227.75,104
  Mid-Layer 2 w0.25: v1(225.057,118.082) 226.825,116.313 v1@226.825,105.05
NetJ1_1: J1.1 L2.1 | length 4.4
  Bottom Layer w0.5: J1.1@168.212,136.9 170.15,136.9 170.15,139.15 L2.1@170.325,139.325
NETLIGHT: R5.1 U1.52 | length 59.4
  Top Layer w0.25: v1@183.85,148.3 183.975,148.175 184.05,148.1 184.05,147.125 184.925,146.25 U1.52@185.95,146.25
  Mid-Layer 1 w0.25: v1(184.1,148.3) 185.075,147.325 206.415,147.325 207.515,146.225 213.275,146.225 213.545,146.495 217.105,146.495 222.35,141.25 222.35,131.075 v1(223.625,129.8)
  Bottom Layer w0.25: R5.1@222,128.25 222,128.53 223.447,129.978 223.47,130 v1@223.625,130
NETLIGHT_CPU: R5.2 R7.1 U3.39 | length 28.1
  Top Layer w0.25: v2(216.025,108.775) 216.304,108.775 217.765,110.236 U3.39@219.136,110.236
  Mid-Layer 1 w0.25: v2@216.39,108.818 216.6,109.029 216.6,109.074 219.335,111.809 219.335,116.425 222.425,119.515 222.425,121.3 224.875,123.75 224.875,128.425 v1@224.8,128.5
  Bottom Layer w0.25: R5.2@223.5,128.5 224.55,128.5 v1@224.65,128.5
  other v1: 224.55,128.55
NetLS2_1: LS2.1 U16.23 | length 5.5
  Top Layer w0.25: LS2.1@174.25,113.5 174.825,114.075 178.325,114.075 178.75,113.65 U16.23@178.75,113.05
NetLS2_2: LS2.2 U16.25 | length 5.2
  Top Layer w0.22: LS2.2@174.4,111.2 174.4,111.625 174.783,112.008
  Top Layer w0.24: 174.783,112.008 175.384,112.609 ; 175.37,112.622 175.37,112.945 175.85,113.425 176.7,113.425 177.45,112.675 U16.25@177.45,112.25
NetP2_1: P2.1 U1.60 | length 6.3
  Top Layer w0.55: P2.1@179.75,138.25 P2.1@179.8,138.2
  Top Layer w0.6: P2.1@179.8,138.2 U1.60@186,138.2
NetQ1_1: Q1.1 R6.2 R8.1 | length 4.3
  Bottom Layer w0.3: Q1.1@220.55,123.2 220.75,123 R8.1@222.5,123 R6.2@224.75,123
NetQ2_3: Q2.3 R17.2 | length 1.3
  Bottom Layer w0.3: R17.2@216.75,143.3 216.75,143.925 Q2.3@217.237,144.412
NetQ3_1: Q3.1 R30.1 R31.2 | length 4.7
  Bottom Layer w0.3: R31.2@198.2,140.3 Q3.1@198.2,141.7 198.2,142.275 199.825,143.9 R30.1@200.25,143.9
NetQ4_1: Q4.1 R33.1 R34.2 | length 3.3
  Bottom Layer w0.25: R33.1@180.35,123.5 R33.1@180.35,123.25 180.35,122.15 Q4.1@180.8,121.7 ; Q4.1@180.95,121.7 R34.2@182.25,121.7
NetQ5_1: Q5.1 R35.1 R38.2 | length 3.5
  Top Layer w0.3: R35.1@220.15,139.5 220.2,139.45 220.2,137.5 Q5.1@220.2,136.15 Q5.1@220.2,136.05
NetQ6_1: Q6.1 R43.2 R47.1 | length 53.2
  Top Layer w0.3: R43.2@172.65,132.75 v1(173.425,132.75) 174.25,132.75 Q6.1@174.45,132.95
  Mid-Layer 1 w0.3: v1@173.65,132.75 v1(173.425,132.75) 172.9,132.75 171.25,131.1 171.25,128.75 172.75,127.25 195.075,127.25 v1@198.238,124.087
  Bottom Layer w0.3: v1@198.125,123.975 198.25,123.975 200.575,121.65 207.377,121.65 211.377,125.65 212.37,125.65 R47.1@212.435,125.585
  other v1: 198.125,123.925
NetQ7_3: Q7.3 R45.1 | length 3.8
  Top Layer w0.25: Q7.3@227.6,144.25 229.15,144.25 230.15,143.25 R45.1@230.95,143.25
NetQ8_1: Q8.1 R52.1 | length 2.3
  Top Layer w0.25: R52.1@218.75,125.55 219.55,125.55 219.921,125.921 219.931,125.931 v1(219.911,125.931)
  Bottom Layer w0.25: v1(219.911,125.931) 219.931,125.931 220.375,126.375 220.55,126.55
NetQ8_3: Q8.3 R47.2 | length 3.5
  Bottom Layer w0.25: R47.2@214.65,125.75 217.525,125.75 Q8.3@217.975,125.3
NetR1_2: R1.2 VD1.1 | length 2
  Top Layer w0.25: R1.2@177,146.8 177.2,147 VD1.1@177.2,148.75
NetR2_2: R2.2 VD1.2 | length 2.3
  Top Layer w0.25: R2.2@175,146.8 175.8,147.6 VD1.2@175.8,148.75
NetR4_2: R4.2 VD1.4 | length 1.7
  Top Layer w0.25: R4.2@173,147.05 VD1.4@173,148.75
